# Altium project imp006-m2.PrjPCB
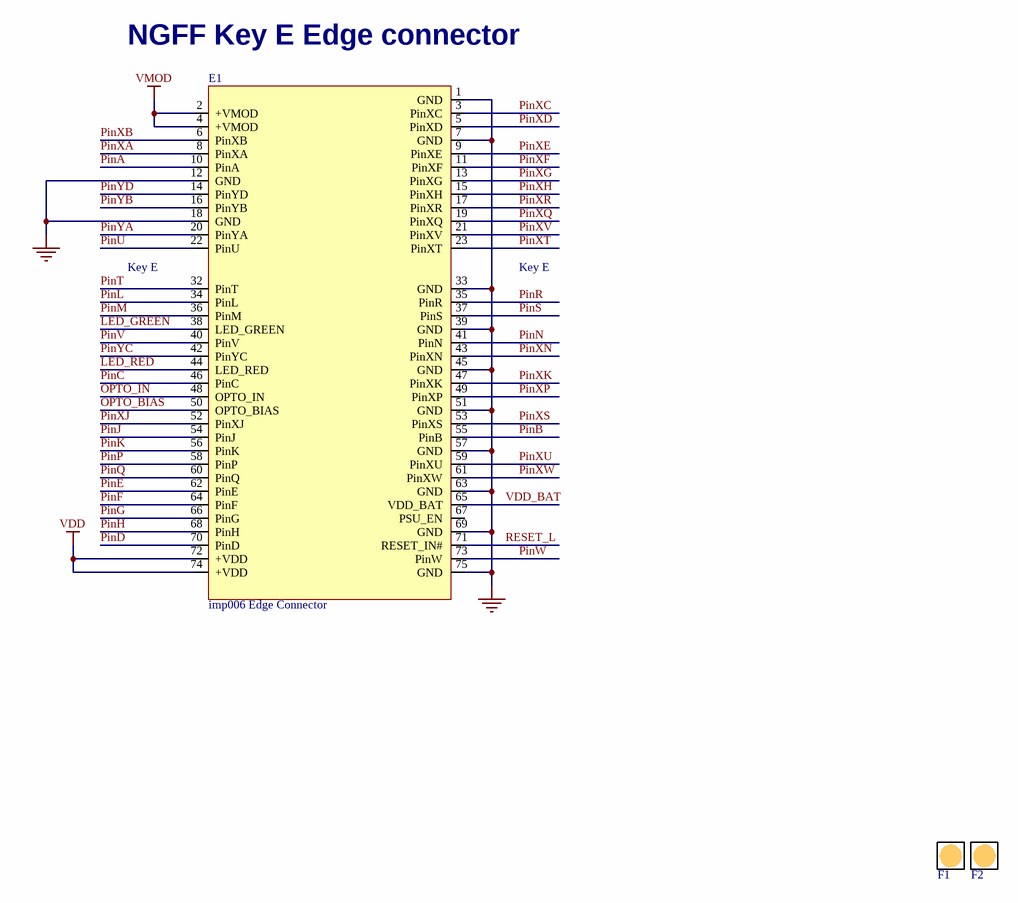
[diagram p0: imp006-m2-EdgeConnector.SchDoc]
3 sheets, 78 parts. Net scope: global (net labels, ports and power ports of the same name join across sheets).
Board file: imp006-m2.PcbDoc
Sheets:
  imp006-m2-EdgeConnector.SchDoc
  imp006-m2-MCU.SchDoc
  imp006-m2-BG96.SchDoc

## Sheet imp006-m2-EdgeConnector.SchDoc: imp006-m2
size Tabloid; Revision: 2.0; SheetNumber: 1; SheetTotal: 3; PageSetup: Record=PageOptions¦CenterHorizontal=True¦CenterVertical=True¦PrintScale=0.62¦XCorrection=1.00¦YCorrection=1.00¦PrintKind=1¦BorderSize=5000000¦LeftOffset=0¦BottomOffset=0¦Orientation=2¦PaperLength=1000¦PaperWidth=1000¦Scale=100¦PaperSource=279¦PrintQuality=-3¦MediaType=1¦DitherType=10¦PrintScaleMode=1¦PaperKind=Letter 8.5"x11" 22x28cm¦PaperIndex=1

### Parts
E1  imp006 Edge Connector  [NGFF_EDGE75_E]  (no BOM)
F1  Fiducial  [FIDUCIAL1MM]  (value not drawn)  (net tie, no BOM)
F2  Fiducial  [FIDUCIAL1MM]  (value not drawn)  (net tie, no BOM)

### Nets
GND: E1.1(GND) E1.7(GND) E1.12(GND) E1.18(GND) E1.33(GND) E1.39(GND) E1.45(GND) E1.51(GND) E1.57(GND) E1.63(GND) E1.69(GND) E1.75(GND)
VDD: E1.72(+VDD) E1.74(+VDD)
VMOD: E1.2(+VMOD) E1.4(+VMOD)
LED_GREEN: E1.38(LED_GREEN)
LED_RED: E1.44(LED_RED)
OPTO_BIAS: E1.50(OPTO_BIAS)
OPTO_IN: E1.48(OPTO_IN)
PinA: E1.10(PinA)
PinB: E1.55(PinB)
PinC: E1.46(PinC)
PinD: E1.70(PinD)
PinE: E1.62(PinE)
PinF: E1.64(PinF)
PinG: E1.66(PinG)
PinH: E1.68(PinH)
PinJ: E1.54(PinJ)
PinK: E1.56(PinK)
PinL: E1.34(PinL)
PinM: E1.36(PinM)
PinN: E1.41(PinN)
PinP: E1.58(PinP)
PinQ: E1.60(PinQ)
PinR: E1.35(PinR)
PinS: E1.37(PinS)
PinT: E1.32(PinT)
PinU: E1.22(PinU)
PinV: E1.40(PinV)
PinW: E1.73(PinW)
PinXA: E1.8(PinXA)
PinXB: E1.6(PinXB)
PinXC: E1.3(PinXC)
PinXD: E1.5(PinXD)
PinXE: E1.9(PinXE)
PinXF: E1.11(PinXF)
PinXG: E1.13(PinXG)
PinXH: E1.15(PinXH)
PinXJ: E1.52(PinXJ)
PinXK: E1.47(PinXK)
PinXN: E1.43(PinXN)
PinXP: E1.49(PinXP)
PinXQ: E1.19(PinXQ)
PinXR: E1.17(PinXR)
PinXS: E1.53(PinXS)
PinXT: E1.23(PinXT)
PinXU: E1.59(PinXU)
PinXV: E1.21(PinXV)
PinXW: E1.61(PinXW)
PinYA: E1.20(PinYA)
PinYB: E1.16(PinYB)
PinYC: E1.42(PinYC)
PinYD: E1.14(PinYD)
RESET_L: E1.71(RESET_IN#)
VDD_BAT: E1.65(VDD_BAT)

Not connected (* = marked no-connect by the designer): E1 67(PSU_EN)

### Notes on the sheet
- (near E1) NGFF Key E Edge connector
- (near E1) Key E
- Key E

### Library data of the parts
E1 = CON00098: Edge Connector, NGFF Key E
F1 F2 = ELEC00015

## Sheet imp006-m2-MCU.SchDoc: imp006-m2
size Tabloid; Revision: 2.0; SheetNumber: 2; SheetTotal: 3
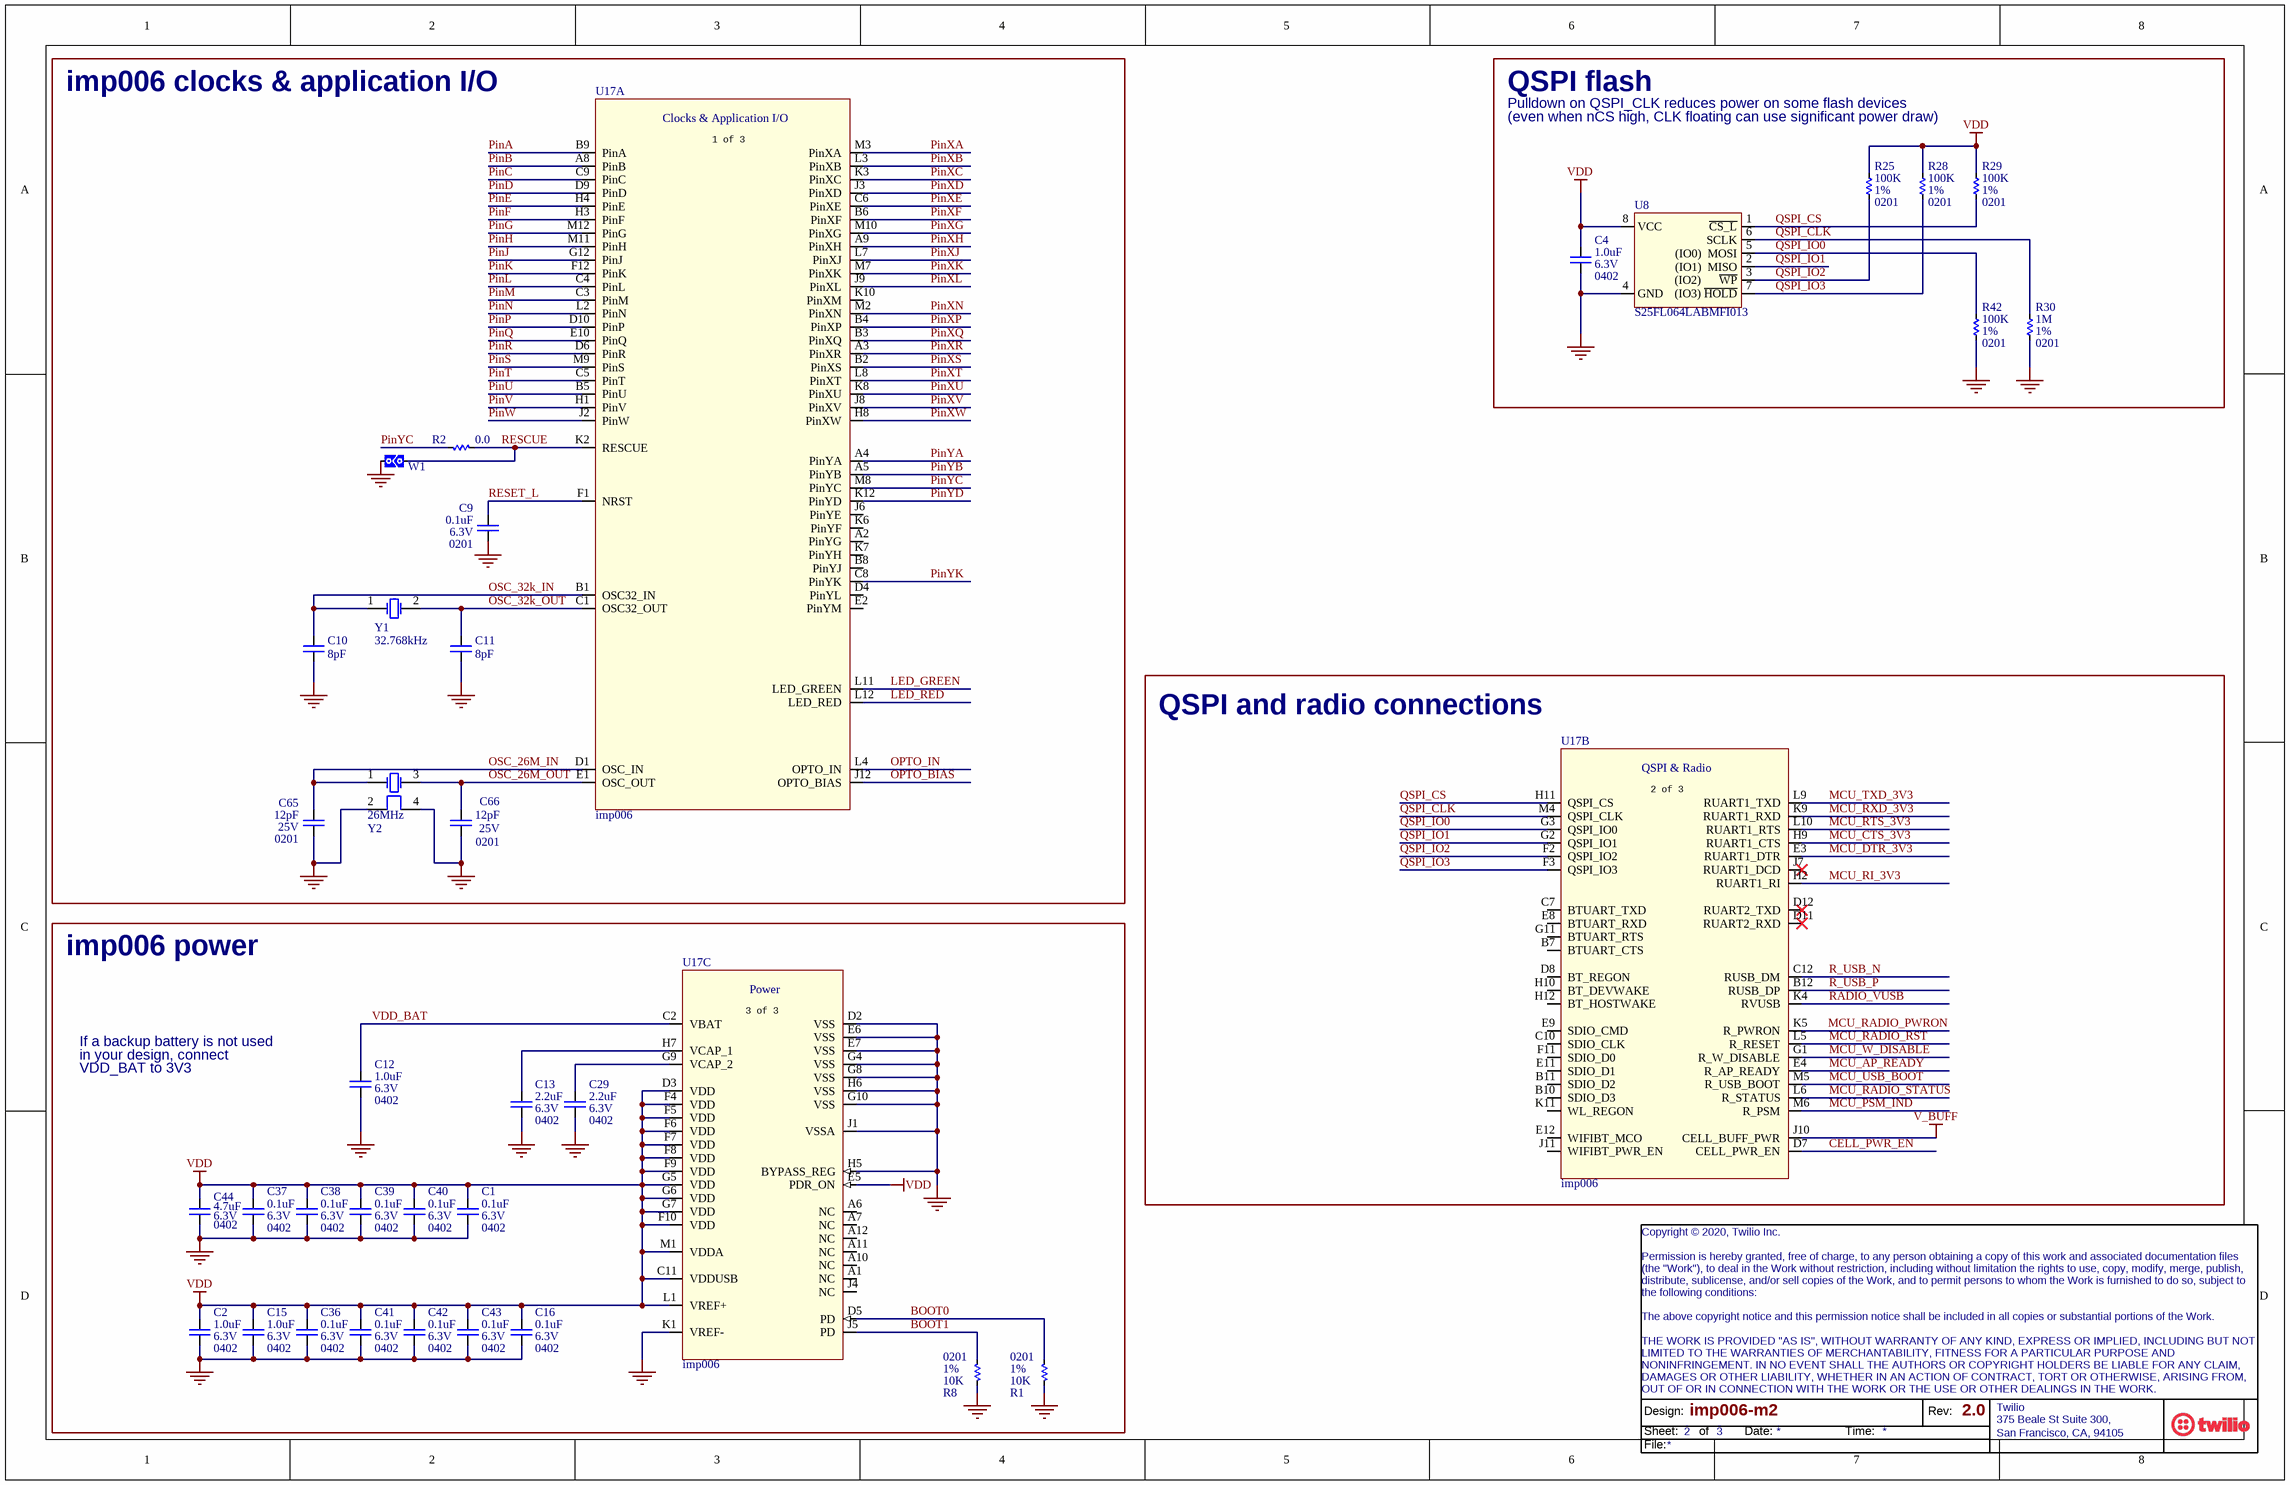
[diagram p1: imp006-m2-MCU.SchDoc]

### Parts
C1  value 0.1uF  Voltage: 6.3V  Package: 0402  [CAPC1005X07M]  (hidden comment: Ceramic Capacitor)
C2  value 1.0uF  Voltage: 6.3V  Package: 0402  [CAPC1005X07M]  (hidden comment: Ceramic Capacitor)
C4  value 1.0uF  Voltage: 6.3V  Package: 0402  [CAPC1005X07M]  (hidden comment: Ceramic Capacitor)
C9  value 0.1uF  Voltage: 6.3V  Package: 0201  [CAPC0603X03N]  (hidden comment: Ceramic Capacitor)
C10  value 8pF  [CAPC0603X03N]  (hidden comment: Ceramic Capacitor)
C11  value 8pF  [CAPC0603X03N]  (hidden comment: Ceramic Capacitor)
C12  value 1.0uF  Voltage: 6.3V  Package: 0402  [CAPC1005X07M]  (hidden comment: Ceramic Capacitor)
C13  value 2.2uF  Voltage: 6.3V  Package: 0402  [CAPC1005X07M]  (hidden comment: Ceramic Capacitor)
C15  value 1.0uF  Voltage: 6.3V  Package: 0402  [CAPC1005X07M]  (hidden comment: Ceramic Capacitor)
C16  value 0.1uF  Voltage: 6.3V  Package: 0402  [CAPC1005X07M]  (hidden comment: Ceramic Capacitor)
C29  value 2.2uF  Voltage: 6.3V  Package: 0402  [CAPC1005X07M]  (hidden comment: Ceramic Capacitor)
C36  value 0.1uF  Voltage: 6.3V  Package: 0402  [CAPC1005X07M]  (hidden comment: Ceramic Capacitor)
C37  value 0.1uF  Voltage: 6.3V  Package: 0402  [CAPC1005X07M]  (hidden comment: Ceramic Capacitor)
C38  value 0.1uF  Voltage: 6.3V  Package: 0402  [CAPC1005X07M]  (hidden comment: Ceramic Capacitor)
C39  value 0.1uF  Voltage: 6.3V  Package: 0402  [CAPC1005X07M]  (hidden comment: Ceramic Capacitor)
C40  value 0.1uF  Voltage: 6.3V  Package: 0402  [CAPC1005X07M]  (hidden comment: Ceramic Capacitor)
C41  value 0.1uF  Voltage: 6.3V  Package: 0402  [CAPC1005X07M]  (hidden comment: Ceramic Capacitor)
C42  value 0.1uF  Voltage: 6.3V  Package: 0402  [CAPC1005X07M]  (hidden comment: Ceramic Capacitor)
C43  value 0.1uF  Voltage: 6.3V  Package: 0402  [CAPC1005X07M]  (hidden comment: Ceramic Capacitor)
C44  value 4.7uF  Voltage: 6.3V  Package: 0402  [CAPC1005X07M]  (hidden comment: Ceramic Capacitor)
C65  value 12pF  Voltage: 25V  Package: 0201  [CAPC0603X03N]  (hidden comment: Ceramic Capacitor)
C66  value 12pF  Voltage: 25V  Package: 0201  [CAPC0603X03N]  (hidden comment: Ceramic Capacitor)
R1  value 10K  Package: 0201  Tolerance: 1%  [RESC0603X03M]  (hidden comment: Resistor)
R2  value 0.0  [RESC1005X04M]  (hidden comment: Resistor)
R8  value 10K  Package: 0201  Tolerance: 1%  [RESC0603X03M]  (hidden comment: Resistor)
R25  value 100K  Package: 0201  Tolerance: 1%  [RESC0603X03M]  (hidden comment: Resistor)
R28  value 100K  Package: 0201  Tolerance: 1%  [RESC0603X03M]  (hidden comment: Resistor)
R29  value 100K  Package: 0201  Tolerance: 1%  [RESC0603X03M]  (hidden comment: Resistor)
R30  value 1M  Package: 0201  Tolerance: 1%  [RESC0603X03M]  (hidden comment: Resistor)
R42  value 100K  Package: 0201  Tolerance: 1%  [RESC0603X03M]  (hidden comment: Resistor)
U8  Manufacturer Part Number: S25FL064LABMFI013  [SOP127P790X216-8N]  (hidden comment: MX25R6435FZAIH0)
U17  imp006  [STM-UFBGA144]  (parts A,B,C of 3)
W1  Shortpads  [SHORTBRIDGE]  (value not drawn)  (no BOM)
Y1  Frequency: 32.768kHz  [XTAL_20X12X06-2N]  (hidden comment: XTAL)
Y2  Frequency: 26MHz  [XTAL_20X16X07-4N]  (hidden comment: XTAL_20X16_26MHZ)

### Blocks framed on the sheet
imp006 clocks & application I/O: C9-C11 C65 C66 R2 U17 W1 Y1 Y2
QSPI flash: C4 R25 R28-R30 R42 U8
QSPI and radio connections: U17
imp006 power: C1 C2 C12 C13 C15 C16 C29 C36-C44 R1 R8 U17

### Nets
GND: C1.1 C2.1 C4.1 C9.1 C10.1 C11.1 C12.1 C13.1 C15.1 C16.1 C29.1 C36.1 C37.1 C38.1 C39.1 C40.1 C41.1 C42.1 C43.1 C44.1 C65.1 C66.1 R1.2 R8.2 R30.2 R42.2 U8.4(GND) U17.D2(VSS) U17.E6(VSS) U17.E7(VSS) U17.G4(VSS) U17.G8(VSS) U17.G10(VSS) U17.H5(BYPASS_REG) U17.H6(VSS) U17.J1(VSSA) U17.K1(VREF-) W1.2 Y2.2(GND) Y2.4(GND)
V_BUFF: U17.J10(CELL_BUFF_PWR)
VDD: C1.2 C2.2 C4.2 C15.2 C16.2 C36.2 C37.2 C38.2 C39.2 C40.2 C41.2 C42.2 C43.2 C44.2 R25.1 R28.1 R29.1 U8.8(VCC) U17.C11(VDDUSB) U17.D3(VDD) U17.E5(PDR_ON) U17.F4(VDD) U17.F5(VDD) U17.F6(VDD) U17.F7(VDD) U17.F8(VDD) U17.F9(VDD) U17.F10(VDD) U17.G5(VDD) U17.G6(VDD) U17.G7(VDD) U17.L1(VREF+) U17.M1(VDDA)
BOOT0: R1.1 U17.D5(PD)
BOOT1: R8.1 U17.J5(PD)
CELL_PWR_EN: U17.D7(CELL_PWR_EN)
LED_GREEN: U17.L11(LED_GREEN)
LED_RED: U17.L12(LED_RED)
MCU_AP_READY: U17.E4(R_AP_READY)
MCU_CTS_3V3: U17.H9(RUART1_CTS)
MCU_DTR_3V3: U17.E3(RUART1_DTR)
MCU_PSM_IND: U17.M6(R_PSM)
MCU_RADIO_PWRON: U17.K5(R_PWRON)
MCU_RADIO_RST: U17.L5(R_RESET)
MCU_RADIO_STATUS: U17.L6(R_STATUS)
MCU_RI_3V3: U17.H2(RUART1_RI)
MCU_RTS_3V3: U17.L10(RUART1_RTS)
MCU_RXD_3V3: U17.K9(RUART1_RXD)
MCU_TXD_3V3: U17.L9(RUART1_TXD)
MCU_USB_BOOT: U17.M5(R_USB_BOOT)
MCU_W_DISABLE: U17.G1(R_W_DISABLE)
OPTO_BIAS: U17.J12(OPTO_BIAS)
OPTO_IN: U17.L4(OPTO_IN)
OSC_26M_IN: C65.2 U17.D1(OSC_IN) Y2.1(OSC1)
OSC_26M_OUT: C66.2 U17.E1(OSC_OUT) Y2.3(OSC2)
OSC_32k_IN: C10.2 U17.B1(OSC32_IN) Y1.1(OSC1)
OSC_32k_OUT: C11.2 U17.C1(OSC32_OUT) Y1.2(OSC2)
PinA: U17.B9(PinA)
PinB: U17.A8(PinB)
PinC: U17.C9(PinC)
PinD: U17.D9(PinD)
PinE: U17.H4(PinE)
PinF: U17.H3(PinF)
PinG: U17.M12(PinG)
PinH: U17.M11(PinH)
PinJ: U17.G12(PinJ)
PinK: U17.F12(PinK)
PinL: U17.C4(PinL)
PinM: U17.C3(PinM)
PinN: U17.L2(PinN)
PinP: U17.D10(PinP)
PinQ: U17.E10(PinQ)
PinR: U17.D6(PinR)
PinS: U17.M9(PinS)
PinT: U17.C5(PinT)
PinU: U17.B5(PinU)
PinV: U17.H1(PinV)
PinW: U17.J2(PinW)
PinXA: U17.M3(PinXA)
PinXB: U17.L3(PinXB)
PinXC: U17.K3(PinXC)
PinXD: U17.J3(PinXD)
PinXE: U17.C6(PinXE)
PinXF: U17.B6(PinXF)
PinXG: U17.M10(PinXG)
PinXH: U17.A9(PinXH)
PinXJ: U17.L7(PinXJ)
PinXK: U17.M7(PinXK)
PinXL: U17.J9(PinXL)
PinXN: U17.M2(PinXN)
PinXP: U17.B4(PinXP)
PinXQ: U17.B3(PinXQ)
PinXR: U17.A3(PinXR)
PinXS: U17.B2(PinXS)
PinXT: U17.L8(PinXT)
PinXU: U17.K8(PinXU)
PinXV: U17.J8(PinXV)
PinXW: U17.H8(PinXW)
PinYA: U17.A4(PinYA)
PinYB: U17.A5(PinYB)
PinYC: R2.2 U17.M8(PinYC)
PinYD: U17.K12(PinYD)
PinYK: U17.C8(PinYK)
QSPI_CLK: R30.1 U8.6(SCLK) U17.M4(QSPI_CLK)
QSPI_CS: R29.2 U8.1(~{CS_L}) U17.H11(QSPI_CS)
QSPI_IO0: R42.1 U8.5((IO0)__MOSI) U17.G3(QSPI_IO0)
QSPI_IO1: U8.2((IO1)__MISO) U17.G2(QSPI_IO1)
QSPI_IO2: R25.2 U8.3((IO2)______~{WP}) U17.F2(QSPI_IO2)
QSPI_IO3: R28.2 U8.7((IO3)_~{HOLD}) U17.F3(QSPI_IO3)
R_USB_N: U17.C12(RUSB_DM)
R_USB_P: U17.B12(RUSB_DP)
RADIO_VUSB: U17.K4(RVUSB)
RESCUE: R2.1 U17.K2(RESCUE) W1.1
RESET_L: C9.2 U17.F1(NRST)
VDD_BAT: C12.2 U17.C2(VBAT)
NetC13_2: C13.2 U17.H7(VCAP_1)
NetC29_2: C29.2 U17.G9(VCAP_2)

Not connected (* = marked no-connect by the designer): U17 A1(NC) A2(PinYG) A6(NC) A7(NC) A10(NC) A11(NC) A12(NC) B7(BTUART_CTS) B8(PinYJ) B10(SDIO_D3) B11(SDIO_D2) C7(BTUART_TXD) C10(SDIO_CLK) D4(PinYL) D8(BT_REGON) D11(RUART2_RXD)* D12(RUART2_TXD)* E2(PinYM) E8(BTUART_RXD) E9(SDIO_CMD) E11(SDIO_D1) E12(WIFIBT_MCO) F11(SDIO_D0) G11(BTUART_RTS) H10(BT_DEVWAKE) H12(BT_HOSTWAKE) J4(NC) J6(PinYE) J7(RUART1_DCD)* J11(WIFIBT_PWR_EN) K6(PinYF) K7(PinYH) K10(PinXM) K11(WL_REGON)

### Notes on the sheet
- Pulldown on QSPI_CLK reduces power on some flash devices
- (even when nCS high, CLK floating can use significant power draw)
- If a backup battery is not used
- in your design, connect
- VDD_BAT to 3V3

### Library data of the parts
C1 C16 C36-C43 = CAPC00002: CAP,X5R,0.1uF,10%,6.3V, 0402,#; Manufacturer: TDK; Manufacturer Part Number: C1005X5R0J104K
C2 C4 C12 C15 = CAPC00005: CAP,X5R,1.0uF,10%,6.3V, 0402,#; Manufacturer: Murata; Manufacturer Part Number: GRM155R60J105KE19D
C9 = CAPC00073: CAP,X5R,0.1uF,20%,6.3V,0201; Manufacturer: TDK; Manufacturer Part Number: C0603X5R0J104M030BC
C10 C11 = CAPC00146: CAP,C0G,8pF,±0.5pF,50V,0201; Manufacturer: Yageo; Manufacturer Part Number: CC0201DRNPO9BN8R0
C13 C29 = CAPC00040: CAP,X5R,2.2uF,10%,6.3V,0402#; Manufacturer: TDK; Manufacturer Part Number: C1005X5R0J225K
C44 = CAPC00012: CAP,X5R,4.7uF,20%,6.3V, 0402,#; Manufacturer: Murata; Manufacturer Part Number: GRM155R60J475ME47D
C65 C66 = CAPC00072: CAP,C0G,12pF,5%,25V,0201; Manufacturer: Murata; Manufacturer Part Number: GRM0335C1E120JA01D
R1 R8 = RES00074: RES,10K Ohm,1%,0.05W,0201; Manufacturer: Panasonic; Manufacturer Part Number: ERJ-1GEF1002C
R2 = RES00019: RES,0 Ohm,0.063W,0402; Manufacturer: Yageo; Manufacturer Part Number: RC0402JR-070RL; Tolerance: 0%
R25 R28 R29 R42 = RES00067: RES,100K,1%,0.05W,0201; Manufacturer: Vishay Dale; Manufacturer Part Number: CRCW0201100KFNED
R30 = RES00066: RES,1M,1%,0.05W,0201; Manufacturer: Rohm; Manufacturer Part Number: MCR006YRTF1004
U8 = IC00202: IC, SPI Flash, 64Mbit, 104MHz, QSPI, 2.7V-3.6V, SOIC-8W; Manufacturer: Spansion
U17 = MOD00041: IC, STM32F413ZHJ, preprogrammed impOS, 1.5MB Flash, 100Mhz; Manufacturer_Part_Number: stm32f4xxj1; Manufacturer: ST Micro; Vendor: STMicroelectronics
W1 = ELEC00024: Throughhole Shortpads
Y1 = XTAL00031: XTAL, 32.768kHz, 20ppm, 6pF, 90K Ohm, 2012; Manufacturer: ECS; Manufacturer Part Number: ECS-.327-6-12-TR; Load Capacitance: 7pF; Operating Mode: Fundamental
Y2 = XTAL00024: XTAL, 26MHz, 20ppm, 8pF, 100 Ohm, 2016; Manufacturer: NDK; Manufacturer Part Number: NX2016SA-26MHZ-EXS00A-CS06025; Frequency Tolerance: 15ppm; Operating Mode: Fundamental

## Sheet imp006-m2-BG96.SchDoc: imp006-m2
size Tabloid; Revision: 2.0; SheetNumber: 3; SheetTotal: 3
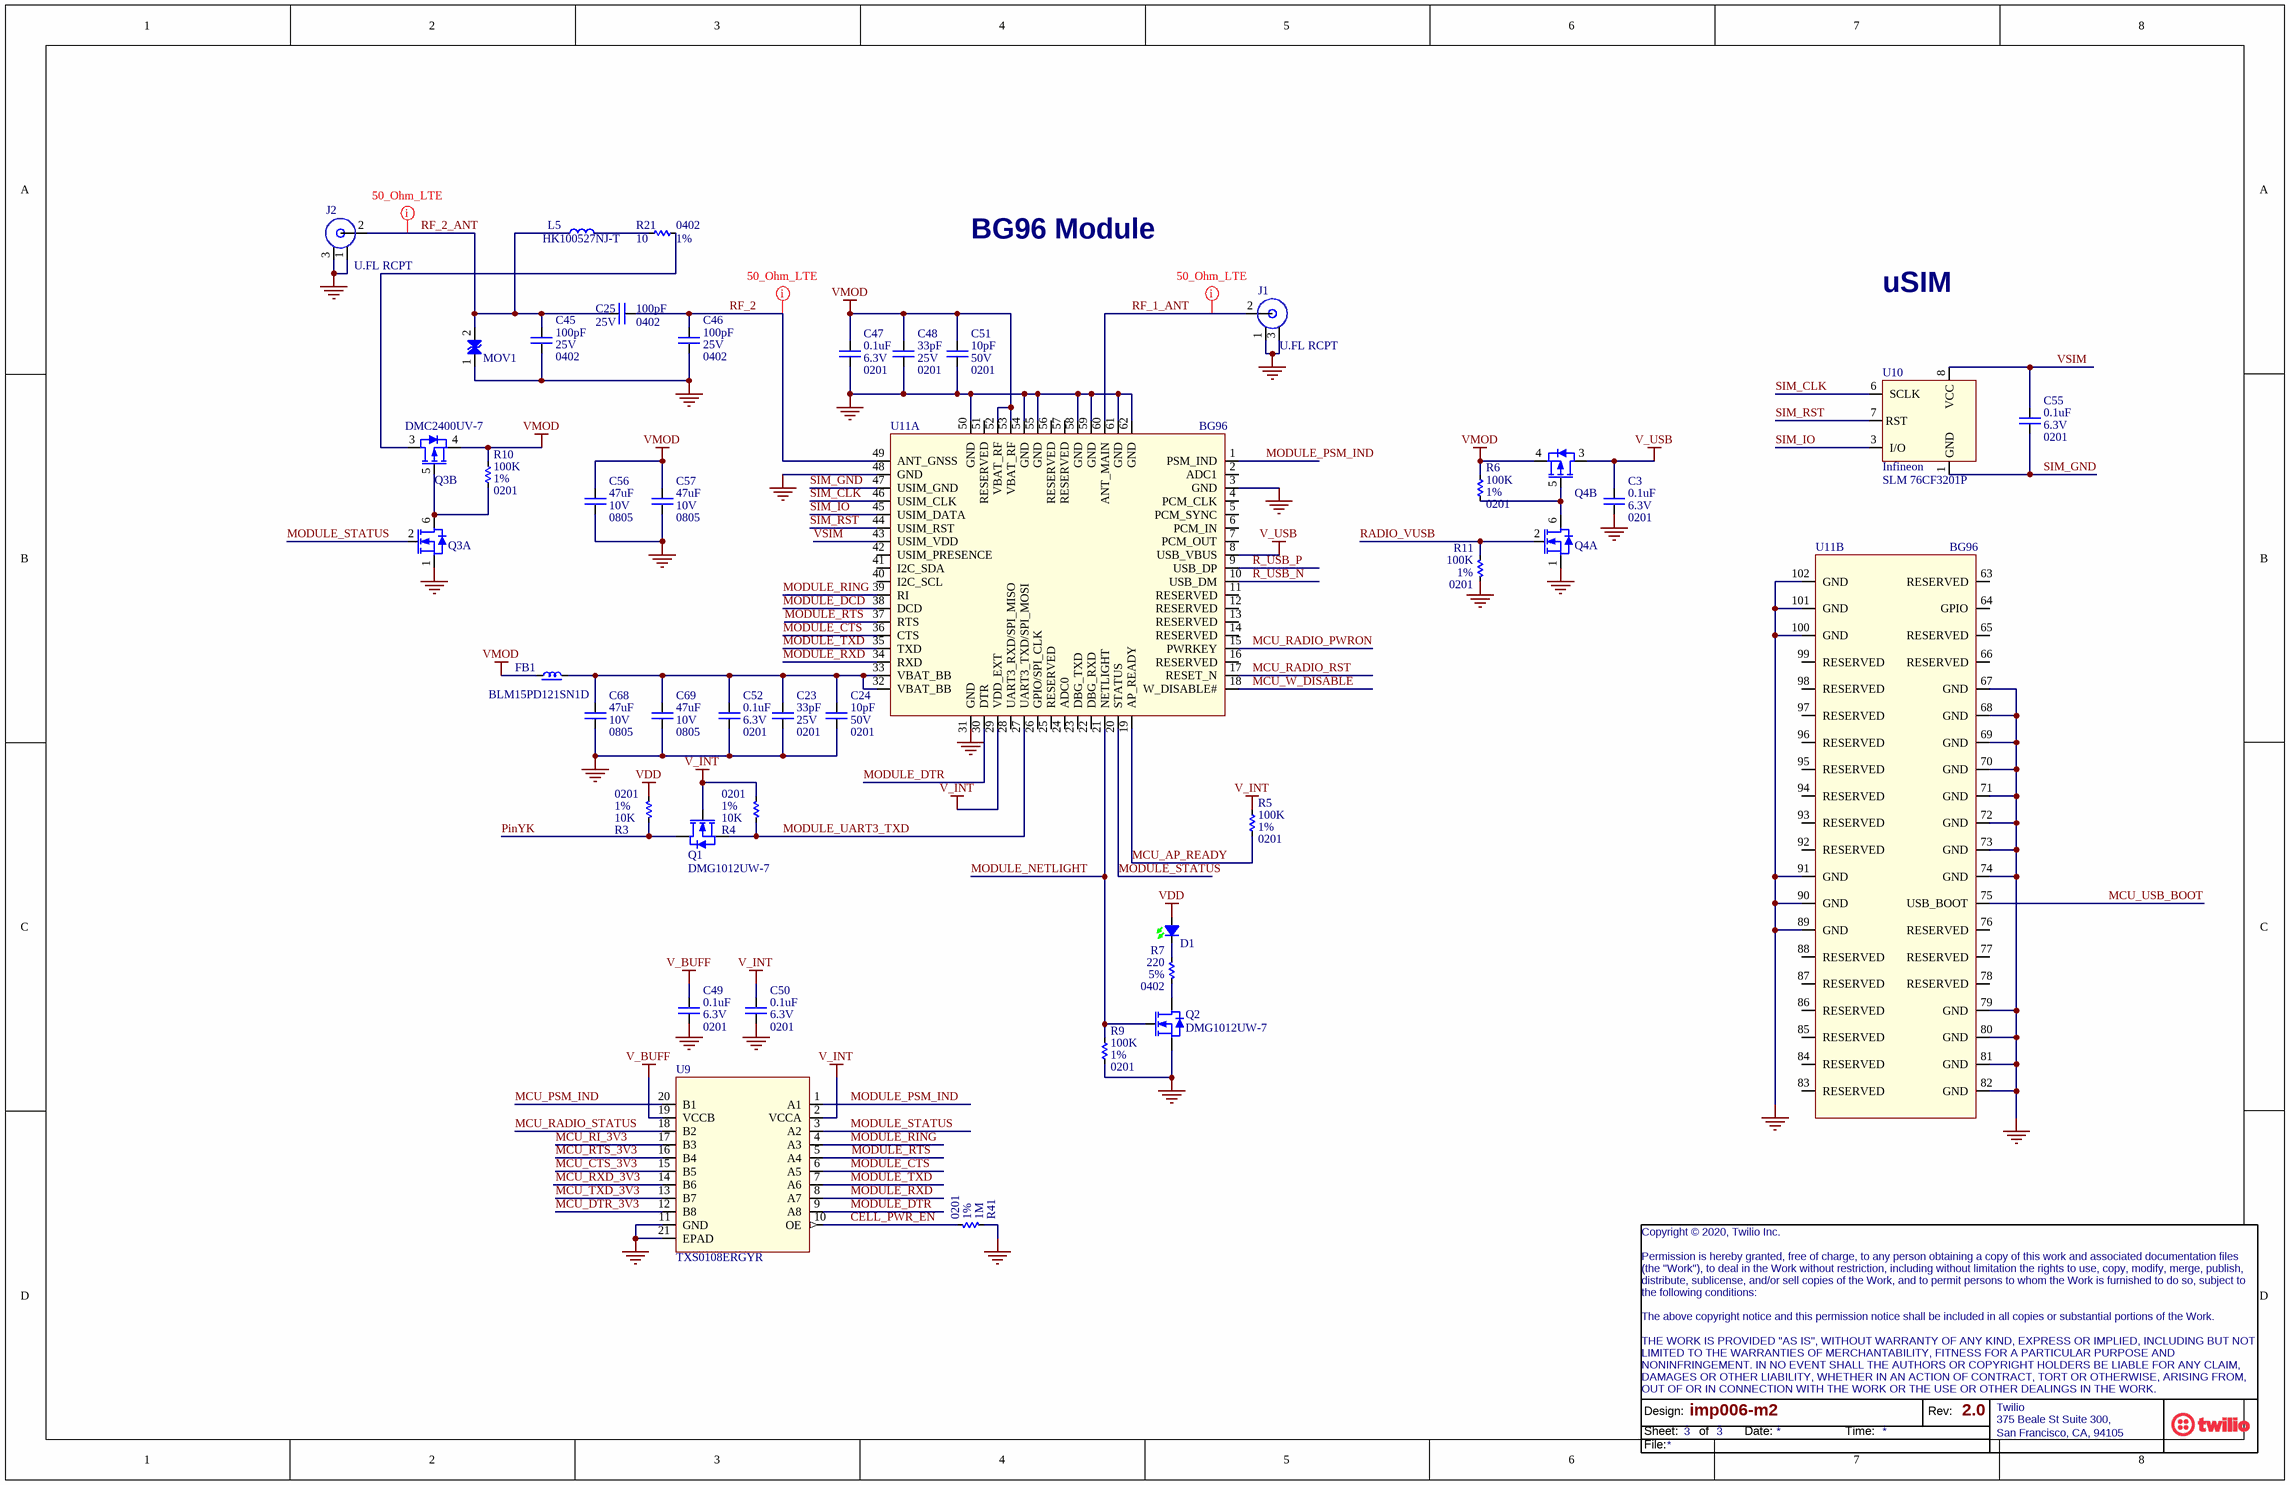
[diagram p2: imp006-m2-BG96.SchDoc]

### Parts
C3  value 0.1uF  Voltage: 6.3V  Package: 0201  [CAPC0603X03N]  (hidden comment: Ceramic Capacitor)
C23  value 33pF  Voltage: 25V  Package: 0201  [CAPC0603X03N]  (hidden comment: Ceramic Capacitor)
C24  value 10pF  Voltage: 50V  Package: 0201  [CAPC0603X03N]  (hidden comment: Ceramic Capacitor)
C25  value 100pF  Voltage: 25V  Package: 0402  [CAPC1005X07M]  (hidden comment: Ceramic Capacitor)
C45  value 100pF  Voltage: 25V  Package: 0402  [CAPC1005X07M]  (hidden comment: Ceramic Capacitor)  (no BOM)
C46  value 100pF  Voltage: 25V  Package: 0402  [CAPC1005X07M]  (hidden comment: Ceramic Capacitor)  (no BOM)
C47  value 0.1uF  Voltage: 6.3V  Package: 0201  [CAPC0603X03N]  (hidden comment: Ceramic Capacitor)
C48  value 33pF  Voltage: 25V  Package: 0201  [CAPC0603X03N]  (hidden comment: Ceramic Capacitor)
C49  value 0.1uF  Voltage: 6.3V  Package: 0201  [CAPC0603X03N]  (hidden comment: Ceramic Capacitor)
C50  value 0.1uF  Voltage: 6.3V  Package: 0201  [CAPC0603X03N]  (hidden comment: Ceramic Capacitor)
C51  value 10pF  Voltage: 50V  Package: 0201  [CAPC0603X03N]  (hidden comment: Ceramic Capacitor)
C52  value 0.1uF  Voltage: 6.3V  Package: 0201  [CAPC0603X03N]  (hidden comment: Ceramic Capacitor)
C55  value 0.1uF  Voltage: 6.3V  Package: 0201  [CAPC0603X03N]  (hidden comment: Ceramic Capacitor)
C56  value 47uF  Voltage: 10V  Package: 0805  [CAPC2012X14N]  (hidden comment: Ceramic Capacitor)
C57  value 47uF  Voltage: 10V  Package: 0805  [CAPC2012X14N]  (hidden comment: Ceramic Capacitor)
C68  value 47uF  Voltage: 10V  Package: 0805  [CAPC2012X14N]  (hidden comment: Ceramic Capacitor)
C69  value 47uF  Voltage: 10V  Package: 0805  [CAPC2012X14N]  (hidden comment: Ceramic Capacitor)
D1  LED Green  [LED1608X08N-GRN]  (value not drawn)
FB1  Manufacturer Part Number: BLM15PD121SN1D  [INDC1005X06M]  (hidden comment: Ferrite Bead)
J1  U.FL RCPT  [RF_RCPT_UFL_400X400]
J2  U.FL RCPT  [RF_RCPT_UFL_400X400]
L5  Manufacturer Part Number: HK100527NJ-T  [INDC1005X06M]  (hidden comment: INDUCTOR)
MOV1  MOV  [CAPC1005X07M]  (value not drawn)
Q1  Manufacturer Part Number: DMG1012UW-7  [SOT65P200X125-3N]  (hidden comment: N-Channel MOSFET)
Q2  Manufacturer Part Number: DMG1012UW-7  [SOT65P200X125-3N]  (hidden comment: N-Channel MOSFET)
Q3  DMC2400UV-7  [SOTFL50P162X66-6N]  (value not drawn)  (parts A,B of 2)
Q4  N-FET + P-FET  [SOTFL50P162X66-6N]  (value not drawn)  (parts A,B of 2)
R3  value 10K  Package: 0201  Tolerance: 1%  [RESC0603X03M]  (hidden comment: Resistor)
R4  value 10K  Package: 0201  Tolerance: 1%  [RESC0603X03M]  (hidden comment: Resistor)
R5  value 100K  Package: 0201  Tolerance: 1%  [RESC0603X03M]  (hidden comment: Resistor)
R6  value 100K  Package: 0201  Tolerance: 1%  [RESC0603X03N]  (hidden comment: Resistor)
R7  value 220  Package: 0402  Tolerance: 5%  [CAPC1005X07M]  (hidden comment: Resistor)
R9  value 100K  Package: 0201  Tolerance: 1%  [RESC0603X03M]  (hidden comment: Resistor)
R10  value 100K  Package: 0201  Tolerance: 1%  [RESC0603X03M]  (hidden comment: Resistor)
R11  value 100K  Package: 0201  Tolerance: 1%  [RESC0603X03N]  (hidden comment: Resistor)
R21  value 10  Package: 0402  Tolerance: 1%  [RESC1005X04M]  (hidden comment: Resistor)
R41  value 1M  Package: 0201  Tolerance: 1%  [RESC0603X03M]  (hidden comment: Resistor)
U9  TXS0108ERGYR  [QFN50P450X350X100_HS-21N]
U10  Manufacturer: Infineon  Manufacturer Part Number: SLM 76CF3201P  [QFN127P600X500X80_HS-9N]  (hidden comment: eSIM)
U11  BG96  [BG96_20170711]  (parts A,B of 2)

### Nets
GND: C3.1 C23.1 C24.1 C45.1 C46.1 C47.1 C48.1 C49.1 C50.1 C51.1 C52.1 C56.1 C57.1 C68.1 C69.1 J1.1(SHLD) J1.3(SHIELD) J2.1(SHLD) J2.3(SHIELD) MOV1.1(A) Q2.2(S) Q3.1(S1) Q4.1(S1) R9.2 R11.2 R41.1 U9.11(GND) U9.21(EPAD) U11.3(GND) U11.31(GND) U11.48(GND) U11.50(GND) U11.54(GND) U11.55(GND) U11.58(GND) U11.59(GND) U11.61(GND) U11.62(GND) U11.67(GND) U11.68(GND) U11.69(GND) U11.70(GND) U11.71(GND) U11.72(GND) U11.73(GND) U11.74(GND) U11.79(GND) U11.80(GND) U11.81(GND) U11.82(GND) U11.89(GND) U11.90(GND) U11.91(GND) U11.100(GND) U11.101(GND) U11.102(GND)
V_BUFF: C49.2 U9.19(VCCB)
V_INT: C50.2 Q1.1(G) R4.1 R5.1 U9.2(VCCA) U11.29(VDD_EXT)
V_USB: C3.2 Q4.3(D2) U11.8(USB_VBUS)
VDD: D1.A R3.1
VMOD: C47.2 C48.2 C51.2 C56.2 C57.2 FB1.1 Q3.4(S2) Q4.4(S2) R6.1 R10.1 U11.52(VBAT_RF) U11.53(VBAT_RF)
CELL_PWR_EN: R41.2 U9.10(OE)
MCU_AP_READY: R5.2 U11.19(AP_READY)
MCU_CTS_3V3: U9.15(B5)
MCU_DTR_3V3: U9.12(B8)
MCU_PSM_IND: U9.20(B1)
MCU_RADIO_PWRON: U11.15(PWRKEY)
MCU_RADIO_RST: U11.17(RESET_N)
MCU_RADIO_STATUS: U9.18(B2)
MCU_RI_3V3: U9.17(B3)
MCU_RTS_3V3: U9.16(B4)
MCU_RXD_3V3: U9.14(B6)
MCU_TXD_3V3: U9.13(B7)
MCU_USB_BOOT: U11.75(USB_BOOT)
MCU_W_DISABLE: U11.18(W_DISABLE#)
MODULE_CTS: U9.6(A5) U11.36(CTS)
MODULE_DCD: U11.38(DCD)
MODULE_DTR: U9.9(A8) U11.30(DTR)
MODULE_NETLIGHT: Q2.1(G) R9.1 U11.21(NETLIGHT)
MODULE_PSM_IND: U9.1(A1) U11.1(PSM_IND)
MODULE_RING: U9.4(A3) U11.39(RI)
MODULE_RTS: U9.5(A4) U11.37(RTS)
MODULE_RXD: U9.8(A7) U11.34(RXD)
MODULE_STATUS: Q3.2(G1) U9.3(A2) U11.20(STATUS)
MODULE_TXD: U9.7(A6) U11.35(TXD)
MODULE_UART3_TXD: Q1.2(S) R4.2 U11.27(UART3_TXD/SPI_MOSI)
PinYK: Q1.3(D) R3.2
R_USB_N: U11.10(USB_DM)
R_USB_P: U11.9(USB_DP)
RADIO_VUSB: Q4.2(G1) R11.1
RF_1_ANT: J1.2(RF) U11.60(ANT_MAIN)
RF_2: C25.2 C46.2 U11.49(ANT_GNSS)
RF_2_ANT: C25.1 C45.2 J2.2(RF) L5.2 MOV1.2(K)
SIM_CLK: U10.6(SCLK) U11.46(USIM_CLK)
SIM_GND: C55.1 U10.1(GND) U11.47(USIM_GND)
SIM_IO: U10.3(I/O) U11.45(USIM_DATA)
SIM_RST: U10.7(RST) U11.44(USIM_RST)
VSIM: C55.2 U10.8(VCC) U11.43(USIM_VDD)
NetC23_2: C23.2 C24.2 C52.2 C68.2 C69.2 FB1.2 U11.32(VBAT_BB) U11.33(VBAT_BB)
NetD1_K: D1.K R7.1
NetL5_1: L5.1 R21.1
NetQ2_3: Q2.3(D) R7.2
NetQ3_3: Q3.3(D2) R21.2
NetQ3_5: Q3.5(G2) Q3.6(D1) R10.2
NetQ4_5: Q4.5(G2) Q4.6(D1) R6.2

Not connected (* = marked no-connect by the designer): U11 2(ADC1) 4(PCM_CLK) 5(PCM_SYNC) 6(PCM_IN) 7(PCM_OUT) 11(RESERVED) 12(RESERVED) 13(RESERVED) 14(RESERVED) 16(RESERVED) 22(DBG_RXD) 23(DBG_TXD) 24(ADC0) 25(RESERVED) 26(GPIO/SPI_CLK) 28(UART3_RXD/SPI_MISO) 40(I2C_SCL) 41(I2C_SDA) 42(USIM_PRESENCE) 51(RESERVED) 56(RESERVED) 57(RESERVED) 63(RESERVED) 64(GPIO) 65(RESERVED) 66(RESERVED) 76(RESERVED) 77(RESERVED) 78(RESERVED) 83(RESERVED) 84(RESERVED) 85(RESERVED) 86(RESERVED) 87(RESERVED) 88(RESERVED) 92(RESERVED) 93(RESERVED) 94(RESERVED) 95(RESERVED) 96(RESERVED) 97(RESERVED) 98(RESERVED) 99(RESERVED)

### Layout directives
net class 50_Ohm_LTE: RF_1_ANT, RF_2, RF_2_ANT

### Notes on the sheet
- BG96 Module
- uSIM

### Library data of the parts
C3 C47 C49 C50 C52 C55 = CAPC00073: as C9 on sheet imp006-m2-MCU
C23 C48 = CAPC00078: CAP,C0G,33pF,5%,25V,0201; Manufacturer: Murata; Manufacturer Part Number: GRM0335C1E330JD01D
C24 C51 = CAPC00143: CAP,C0G,10pF,5%,50V,0201; Manufacturer: Murata; Manufacturer Part Number: GRM0335C1H100JA01D
C25 C45 C46 = CAPC00061: CAP,C0G,100pF,5%,25V,0402; Manufacturer: TDK; Manufacturer Part Number: C1005C0G1E101J
C56 C57 C68 C69 = CAPC00130: CAP,X5R,47uF,20%,10V,0805; Manufacturer: Murata; Manufacturer Part Number: GRM21BR61A476ME15L; BOMOPTION: DNS
D1 = LED00056: LED, Green, 2.8V, 527nm, 5mA, 0603; Manufacturer: Liteon; Manufacturer Part Number: LTST-C193TGKT-5A; Millicandela Rating (min): 154mcd; Wavelength - Dominant: 527.5nm; Wavelength - Peak: 525nm; Viewing Angle: 130º; Lens Type: Clear
FB1 = FB00010: FERR BD, 120 Ohm @ 100Mhz, 1.3 A, 90 mOhm, 0402; Manufacturer: Murata; Impedance @ Frequency: 120 Ohms @ 100MHz; Current Rating: 1.3A; DC Resistance (DCR): 90 mOhm
J1 J2 = CON00013: Conn, Coax, U.FL, non-switch, Rcpt, 2.6 x 2.5mm, SMD; Manufacturer: Hirose; Manufacturer Part Number: U.FL-R-SMT(01)
L5 = IND00041: IND, 27nH, 5%, 700 mOhm, 0402, 300mA; Manufacturer: Taiyo Yuden; DC Resistance (DCR): 700 mOhm (Max)
MOV1 = TVS00012: Varistor,15V,0.05pF,0402; Manufacturer: Murata; Manufacturer Part Number: LXES15AAA1-133; Varistor Voltage: 40VAC
Q1 Q2 = NFET00011: NFET, 20V, 1.A, SOT323; Manufacturer: Diodes Incorporated; Current - Continuous Drain (Id) @ 25° C: 1A; Rds On (Max) @ Id, Vgs: 450mOhm @ 600mA, 4.5V; Vgs(th) (Max) @ Id: 1.0V @ 250uA; Power - Max: 290mW
Q3 = NFET00007: NFET+PFET, 20V, 740mA, SOT563; Manufacturer: Diodes Incorporated; Rds On (Max) @ Id, Vgs: 900mOhm @ 1.8V; Vgs(th) (Max) @ Id: 0.9V @ 250uA; Power - Max: 450mW
Q4 = NFET00007: NFET+PFET, 20V, 740mA, SOT563; Manufacturer: Diodes Incorporated; Manufacturer Part Number: DMC2400UV-7; Rds On (Max) @ Id, Vgs: 900mOhm @ 1.8V; Vgs(th) (Max) @ Id: 0.9V @ 250uA; Power - Max: 450mW
R3 R4 = RES00074: as R1 on sheet imp006-m2-MCU
R5 R6 R9-R11 = RES00067: as R25 on sheet imp006-m2-MCU
R7 = RES00011: RES,220 Ohm,5%,0.063W,0402; Manufacturer: Yageo; Manufacturer Part Number: RC0402JR-07220RL
R21 = RES00071: RES,10 Ohm,1% 0.1W,0402; Manufacturer: Panasonic; Manufacturer Part Number: ERJ-2RKF10R0X
R41 = RES00066: as R30 on sheet imp006-m2-MCU
U9 = IC00267: IC, Logic, 8-bit Level Translator, auto-direction, 20VQFN; Manufacturer: TI; Vendor: Texas Instruments; Built_By: EMA_UL_Team; C: Copyright (C) 2015 Accelerated Designs. All rights reserved
U10 = IC00236: IC, eSIM, SLM 76CF3201P, 320kB Flash, 8kB RAM, 8WSON
U11 = MOD00039: Module, Quectel BG96, LTE Cat M1 + GNSS; Manufacturer Part Number: BG96MA-128-SNN

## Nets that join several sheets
GND: imp006-m2-EdgeConnector (12 pins), imp006-m2-MCU (40 pins), imp006-m2-BG96 (56 pins)
V_BUFF: imp006-m2-MCU (U17.J10), imp006-m2-BG96 (C49.2 U9.19)
VDD: imp006-m2-EdgeConnector (E1.72 E1.74), imp006-m2-MCU (33 pins), imp006-m2-BG96 (D1.A R3.1)
VMOD: imp006-m2-EdgeConnector (E1.2 E1.4), imp006-m2-BG96 (12 pins)
CELL_PWR_EN: imp006-m2-MCU (U17.D7), imp006-m2-BG96 (R41.2 U9.10)
LED_GREEN: imp006-m2-EdgeConnector (E1.38), imp006-m2-MCU (U17.L11)
LED_RED: imp006-m2-EdgeConnector (E1.44), imp006-m2-MCU (U17.L12)
MCU_AP_READY: imp006-m2-MCU (U17.E4), imp006-m2-BG96 (R5.2 U11.19)
MCU_CTS_3V3: imp006-m2-MCU (U17.H9), imp006-m2-BG96 (U9.15)
MCU_DTR_3V3: imp006-m2-MCU (U17.E3), imp006-m2-BG96 (U9.12)
MCU_PSM_IND: imp006-m2-MCU (U17.M6), imp006-m2-BG96 (U9.20)
MCU_RADIO_PWRON: imp006-m2-MCU (U17.K5), imp006-m2-BG96 (U11.15)
MCU_RADIO_RST: imp006-m2-MCU (U17.L5), imp006-m2-BG96 (U11.17)
MCU_RADIO_STATUS: imp006-m2-MCU (U17.L6), imp006-m2-BG96 (U9.18)
MCU_RI_3V3: imp006-m2-MCU (U17.H2), imp006-m2-BG96 (U9.17)
MCU_RTS_3V3: imp006-m2-MCU (U17.L10), imp006-m2-BG96 (U9.16)
MCU_RXD_3V3: imp006-m2-MCU (U17.K9), imp006-m2-BG96 (U9.14)
MCU_TXD_3V3: imp006-m2-MCU (U17.L9), imp006-m2-BG96 (U9.13)
MCU_USB_BOOT: imp006-m2-MCU (U17.M5), imp006-m2-BG96 (U11.75)
MCU_W_DISABLE: imp006-m2-MCU (U17.G1), imp006-m2-BG96 (U11.18)
OPTO_BIAS: imp006-m2-EdgeConnector (E1.50), imp006-m2-MCU (U17.J12)
OPTO_IN: imp006-m2-EdgeConnector (E1.48), imp006-m2-MCU (U17.L4)
PinA: imp006-m2-EdgeConnector (E1.10), imp006-m2-MCU (U17.B9)
PinB: imp006-m2-EdgeConnector (E1.55), imp006-m2-MCU (U17.A8)
PinC: imp006-m2-EdgeConnector (E1.46), imp006-m2-MCU (U17.C9)
PinD: imp006-m2-EdgeConnector (E1.70), imp006-m2-MCU (U17.D9)
PinE: imp006-m2-EdgeConnector (E1.62), imp006-m2-MCU (U17.H4)
PinF: imp006-m2-EdgeConnector (E1.64), imp006-m2-MCU (U17.H3)
PinG: imp006-m2-EdgeConnector (E1.66), imp006-m2-MCU (U17.M12)
PinH: imp006-m2-EdgeConnector (E1.68), imp006-m2-MCU (U17.M11)
PinJ: imp006-m2-EdgeConnector (E1.54), imp006-m2-MCU (U17.G12)
PinK: imp006-m2-EdgeConnector (E1.56), imp006-m2-MCU (U17.F12)
PinL: imp006-m2-EdgeConnector (E1.34), imp006-m2-MCU (U17.C4)
PinM: imp006-m2-EdgeConnector (E1.36), imp006-m2-MCU (U17.C3)
PinN: imp006-m2-EdgeConnector (E1.41), imp006-m2-MCU (U17.L2)
PinP: imp006-m2-EdgeConnector (E1.58), imp006-m2-MCU (U17.D10)
PinQ: imp006-m2-EdgeConnector (E1.60), imp006-m2-MCU (U17.E10)
PinR: imp006-m2-EdgeConnector (E1.35), imp006-m2-MCU (U17.D6)
PinS: imp006-m2-EdgeConnector (E1.37), imp006-m2-MCU (U17.M9)
PinT: imp006-m2-EdgeConnector (E1.32), imp006-m2-MCU (U17.C5)
PinU: imp006-m2-EdgeConnector (E1.22), imp006-m2-MCU (U17.B5)
PinV: imp006-m2-EdgeConnector (E1.40), imp006-m2-MCU (U17.H1)
PinW: imp006-m2-EdgeConnector (E1.73), imp006-m2-MCU (U17.J2)
PinXA: imp006-m2-EdgeConnector (E1.8), imp006-m2-MCU (U17.M3)
PinXB: imp006-m2-EdgeConnector (E1.6), imp006-m2-MCU (U17.L3)
PinXC: imp006-m2-EdgeConnector (E1.3), imp006-m2-MCU (U17.K3)
PinXD: imp006-m2-EdgeConnector (E1.5), imp006-m2-MCU (U17.J3)
PinXE: imp006-m2-EdgeConnector (E1.9), imp006-m2-MCU (U17.C6)
PinXF: imp006-m2-EdgeConnector (E1.11), imp006-m2-MCU (U17.B6)
PinXG: imp006-m2-EdgeConnector (E1.13), imp006-m2-MCU (U17.M10)
PinXH: imp006-m2-EdgeConnector (E1.15), imp006-m2-MCU (U17.A9)
PinXJ: imp006-m2-EdgeConnector (E1.52), imp006-m2-MCU (U17.L7)
PinXK: imp006-m2-EdgeConnector (E1.47), imp006-m2-MCU (U17.M7)
PinXN: imp006-m2-EdgeConnector (E1.43), imp006-m2-MCU (U17.M2)
PinXP: imp006-m2-EdgeConnector (E1.49), imp006-m2-MCU (U17.B4)
PinXQ: imp006-m2-EdgeConnector (E1.19), imp006-m2-MCU (U17.B3)
PinXR: imp006-m2-EdgeConnector (E1.17), imp006-m2-MCU (U17.A3)
PinXS: imp006-m2-EdgeConnector (E1.53), imp006-m2-MCU (U17.B2)
PinXT: imp006-m2-EdgeConnector (E1.23), imp006-m2-MCU (U17.L8)
PinXU: imp006-m2-EdgeConnector (E1.59), imp006-m2-MCU (U17.K8)
PinXV: imp006-m2-EdgeConnector (E1.21), imp006-m2-MCU (U17.J8)
PinXW: imp006-m2-EdgeConnector (E1.61), imp006-m2-MCU (U17.H8)
PinYA: imp006-m2-EdgeConnector (E1.20), imp006-m2-MCU (U17.A4)
PinYB: imp006-m2-EdgeConnector (E1.16), imp006-m2-MCU (U17.A5)
PinYC: imp006-m2-EdgeConnector (E1.42), imp006-m2-MCU (R2.2 U17.M8)
PinYD: imp006-m2-EdgeConnector (E1.14), imp006-m2-MCU (U17.K12)
PinYK: imp006-m2-MCU (U17.C8), imp006-m2-BG96 (Q1.3 R3.2)
R_USB_N: imp006-m2-MCU (U17.C12), imp006-m2-BG96 (U11.10)
R_USB_P: imp006-m2-MCU (U17.B12), imp006-m2-BG96 (U11.9)
RADIO_VUSB: imp006-m2-MCU (U17.K4), imp006-m2-BG96 (Q4.2 R11.1)
RESET_L: imp006-m2-EdgeConnector (E1.71), imp006-m2-MCU (C9.2 U17.F1)
VDD_BAT: imp006-m2-EdgeConnector (E1.65), imp006-m2-MCU (C12.2 U17.C2)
